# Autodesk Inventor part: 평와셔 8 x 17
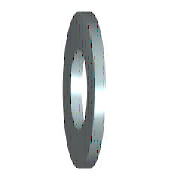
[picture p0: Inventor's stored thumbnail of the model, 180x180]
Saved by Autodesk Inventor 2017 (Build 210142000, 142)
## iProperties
IsCustomPart: 1
Created: 2012-02
Part Number: 평와셔 8 x 17
Material: 강철, 연강
Description: 평면 와셔
Document SubType Name: Modeling
Standard: KS B 1326
Designer: mduedu
Standards Organization: KS
Language: ko-KR
Size Designation: 8x17
Categories: <MemberInstance><Categories><Category DisplayName="조임쇠" InternalName="e4da775c-781d-43d5-af7c-5136215cf5a6" Mnemonic="FSTN"><Category DisplayName="와셔" InternalN
Density: 1 g/cm^3
Appearance: 주황색
Author: mduedu
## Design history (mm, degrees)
sketch "스케치"
  geometry: C1 r 8.5 at (0, 0); C2 r 4.2 at (0, 0); 1 further point
  constraints: 2 centre point, 2 coincident
  dimensions: "d0" = 8.4 diameter of C2 (= SD1); "d1" = 17 diameter of C1 (= SD2)
extrude "본체" new body sketch "스케치" distance "d2" = 1.6 (= SD); taper "d3" = 0 deg
workaxis "Work Axis1"
workplane "Work Plane1"
body "Solid1"
other parameters: "SD1" = 8.4 [user parameter; used in 1 equation term], "SD2" = 17 [user parameter; used in 1 equation term], "SD" = 1.6 [user parameter; used in 1 equation term], "d4" = 0, "d5" = 0, "d6" = 0, "d7" = 0, "NND" = 8 [user parameter]
